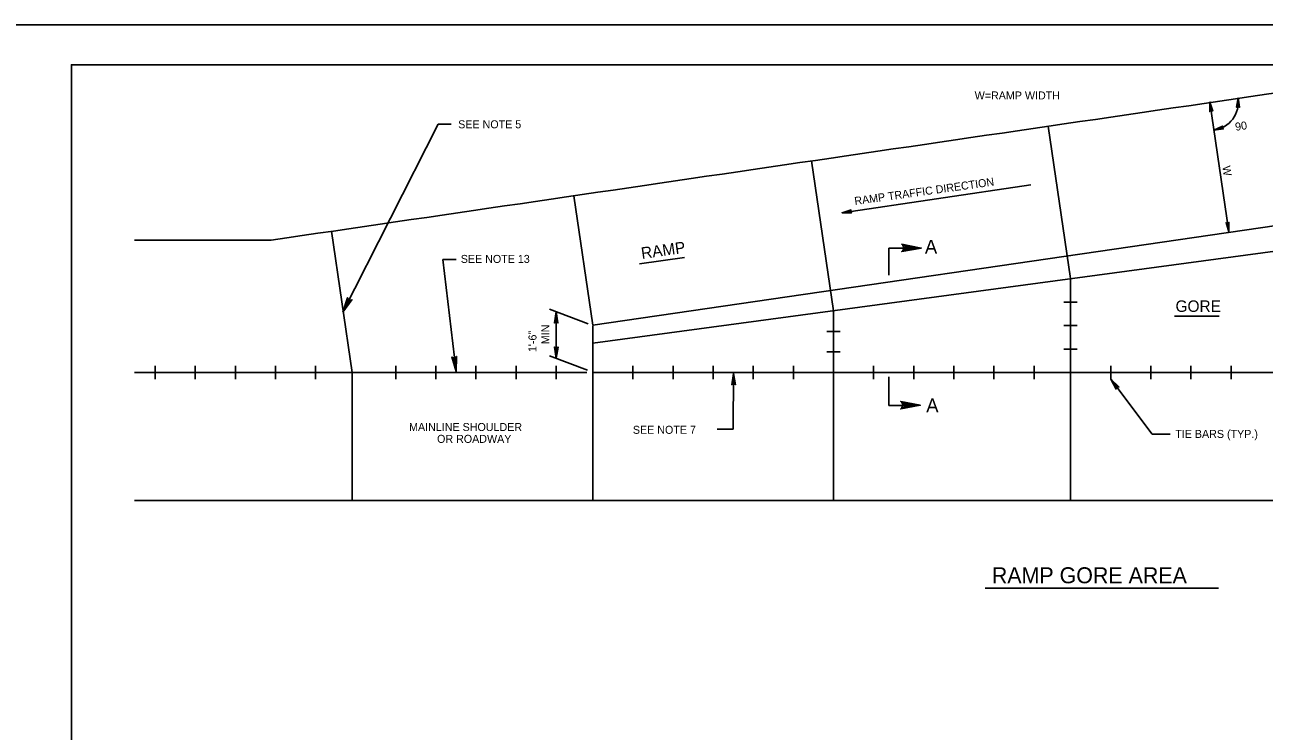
# Model space of a CAD drawing. Extents: x 638216 to 639962, y 297510 to 299292.
# Drawn here: x 639079.4 to 639544, y 299027.4 to 299292.2 of the extents above; entities that cross this region are included whole.
import ezdxf

# ---------------------------------------------------------------- set-up
doc = ezdxf.new("R2010")
doc.units = 0
for name, color, linetype in [('1', 7, 'Continuous'), ('2', 7, 'Continuous'), ('3', 7, 'Continuous'), ('PLT-BNDY', 7, 'Continuous')]:
    doc.layers.add(name, color=color, linetype=linetype)

msp = doc.modelspace()

# ---------------------------------------------------------------- linework, layer by layer
at = {"layer": '1'}
for p, q in [((639292.33, 299179.55), (639839.61, 299259.6)), ((639471.47, 299197.06), (639463.09, 299254.19)), ((639292.35, 299172.88), (639839.61, 299246.75)), ((639382.57, 299184.97), (639374.32, 299241.18)), ((639292.33, 299179.55), (639285.21, 299228.11)), ((639471.47, 299196.97), (639471.47, 299196.97)), ((639471.47, 299188.2), (639471.47, 299188.2)), ((639382.57, 299184.97), (639382.57, 299184.97)), ((639382.57, 299177.28), (639382.57, 299177.28)), ((639471.47, 299179.43), (639471.47, 299179.43)), ((639382.57, 299169.59), (639382.57, 299169.59)), ((639471.47, 299170.67), (639471.47, 299170.67)), ((639128.28, 299161.9), (639134.54, 299161.9)), ((639218.49, 299161.9), (639224.75, 299161.9)), ((639307.39, 299161.9), (639313.65, 299161.9)), ((639344.92, 299140.67), (639345.14, 299161.49)), ((639397.6, 299161.9), (639403.86, 299161.9)), ((639486.5, 299161.9), (639492.76, 299161.9)), ((639501.97, 299138.76), (639486.5, 299159.39)), ((639338.97, 299140.67), (639344.92, 299140.67))]:
    msp.add_line(p, q, dxfattribs=at)
msp.add_lwpolyline([(639882.88, 298713.24), (639882.88, 299277.24), (639096.88, 299277.24), (639096.88, 298713.24), (639882.88, 298713.24), (639882.88, 298739.6), (639682.88, 298739.6), (639682.88, 298804.28), (639882.88, 298804.28), (639882.88, 298833.24), (639682.88, 298833.24), (639682.88, 298713.24), (639761.69, 298713.24), (639761.69, 298739.6), (639761.69, 298713.24), (639838.69, 298713.24), (639838.69, 298739.6), (639838.69, 298727.28), (639882.88, 298727.28)], dxfattribs=at)
msp.add_lwpolyline([(639882.88, 298713.24), (639882.88, 299277.24), (639096.88, 299277.24), (639096.88, 298713.24), (639882.88, 298713.24), (639882.88, 298739.6), (639682.88, 298739.6), (639682.88, 298804.28), (639882.88, 298804.28), (639882.88, 298833.24), (639682.88, 298833.24), (639682.88, 298713.24), (639761.69, 298713.24), (639761.69, 298739.6), (639761.69, 298713.24), (639838.69, 298713.24), (639838.69, 298739.6), (639838.69, 298727.28), (639882.88, 298727.28)], dxfattribs=at)
msp.add_lwpolyline([(639882.88, 298713.24), (639882.88, 299277.24), (639096.88, 299277.24), (639096.88, 298713.24), (639882.88, 298713.24), (639882.88, 298739.6), (639682.88, 298739.6), (639682.88, 298804.28), (639882.88, 298804.28), (639882.88, 298833.24), (639682.88, 298833.24), (639682.88, 298713.24), (639761.69, 298713.24), (639761.69, 298739.6), (639761.69, 298713.24), (639838.69, 298713.24), (639838.69, 298739.6), (639838.69, 298727.28), (639882.88, 298727.28)], dxfattribs=at)
msp.add_lwpolyline([(639882.88, 298713.24), (639882.88, 299277.24), (639096.88, 299277.24), (639096.88, 298713.24), (639882.88, 298713.24), (639882.88, 298739.6), (639682.88, 298739.6), (639682.88, 298804.28), (639882.88, 298804.28), (639882.88, 298833.24), (639682.88, 298833.24), (639682.88, 298713.24), (639761.69, 298713.24), (639761.69, 298739.6), (639761.69, 298713.24), (639838.69, 298713.24), (639838.69, 298739.6), (639838.69, 298727.28), (639882.88, 298727.28)], dxfattribs=at)
msp.add_lwpolyline([(639882.88, 298713.24), (639882.88, 299277.24), (639096.88, 299277.24), (639096.88, 298713.24), (639882.88, 298713.24), (639882.88, 298739.6), (639682.88, 298739.6), (639682.88, 298804.28), (639882.88, 298804.28), (639882.88, 298833.24), (639682.88, 298833.24), (639682.88, 298713.24), (639761.69, 298713.24), (639761.69, 298739.6), (639761.69, 298713.24), (639838.69, 298713.24), (639838.69, 298739.6), (639838.69, 298727.28), (639882.88, 298727.28)], dxfattribs=at)
msp.add_lwpolyline([(639882.88, 298713.24), (639882.88, 299277.24), (639096.88, 299277.24), (639096.88, 298713.24), (639882.88, 298713.24), (639882.88, 298739.6), (639682.88, 298739.6), (639682.88, 298804.28), (639882.88, 298804.28), (639882.88, 298833.24), (639682.88, 298833.24), (639682.88, 298713.24), (639761.69, 298713.24), (639761.69, 298739.6), (639761.69, 298713.24), (639838.69, 298713.24), (639838.69, 298739.6), (639838.69, 298727.28), (639882.88, 298727.28)], dxfattribs=at)
at = {"layer": '2'}
for p, q in [((639234.33, 299255.03), (639198.69, 299184.5)), ((639239.26, 299255.03), (639234.33, 299255.03)), ((639385.78, 299221.78), (639456.57, 299232.18)), ((639202.14, 299161.9), (639194.39, 299214.8)), ((639171.79, 299211.48), (639120.56, 299211.48)), ((639403.26, 299198.38), (639403.26, 299208.53)), ((639403.26, 299208.53), (639412.97, 299208.53)), ((639241.11, 299204.17), (639236.18, 299204.17)), ((639236.18, 299204.17), (639241.09, 299162.24)), ((639309.9, 299202.6), (639326.68, 299205.03)), ((639471.47, 299161.9), (639471.47, 299197.06)), ((639276.14, 299185.61), (639290.55, 299180.05)), ((639473.97, 299188.2), (639468.96, 299188.2)), ((639278.62, 299167.2), (639278.62, 299184.65)), ((639382.57, 299161.9), (639382.57, 299185.06)), ((639510.38, 299182.98), (639527.12, 299182.98)), ((639292.35, 299161.9), (639292.35, 299179.36)), ((639385.07, 299177.28), (639380.06, 299177.28)), ((639473.97, 299179.43), (639468.96, 299179.43)), ((639276.14, 299168.16), (639290.3, 299162.69)), ((639385.07, 299169.59), (639380.06, 299169.59)), ((639473.97, 299170.67), (639468.96, 299170.67)), ((639128.28, 299159.39), (639128.28, 299164.41)), ((639143.31, 299159.39), (639143.31, 299164.41)), ((639158.35, 299159.39), (639158.35, 299164.41)), ((639173.38, 299159.39), (639173.38, 299164.41)), ((639188.42, 299159.39), (639188.42, 299164.41)), ((639218.49, 299159.39), (639218.49, 299164.41)), ((639233.52, 299159.39), (639233.52, 299164.41)), ((639248.56, 299159.39), (639248.56, 299164.41)), ((639263.6, 299159.39), (639263.6, 299164.41)), ((639278.63, 299159.39), (639278.63, 299164.41)), ((639307.39, 299159.39), (639307.39, 299164.41)), ((639322.42, 299159.39), (639322.42, 299164.41)), ((639337.46, 299159.39), (639337.46, 299164.41)), ((639352.49, 299159.39), (639352.49, 299164.41)), ((639367.53, 299159.39), (639367.53, 299164.41)), ((639397.6, 299159.39), (639397.6, 299164.41)), ((639412.64, 299159.39), (639412.64, 299164.41)), ((639427.67, 299159.39), (639427.67, 299164.41)), ((639442.71, 299159.39), (639442.71, 299164.41)), ((639457.74, 299159.39), (639457.74, 299164.41)), ((639486.5, 299159.39), (639486.5, 299164.41)), ((639501.54, 299159.39), (639501.54, 299164.41)), ((639516.57, 299159.39), (639516.57, 299164.41)), ((639531.61, 299159.39), (639531.61, 299164.41)), ((639290.06, 299161.9), (639120.56, 299161.9)), ((639202.14, 299161.9), (639202.14, 299113.9)), ((639292.35, 299161.9), (639292.35, 299113.9)), ((639839.61, 299161.9), (639292.35, 299161.9)), ((639382.57, 299161.9), (639382.57, 299113.9)), ((639403.26, 299149.49), (639403.26, 299160.29)), ((639471.47, 299161.9), (639471.47, 299113.9)), ((639403.26, 299149.49), (639412.97, 299149.49)), ((639508.79, 299138.76), (639501.97, 299138.76)), ((639875.5, 299113.9), (639120.56, 299113.9)), ((639439.38, 299080.98), (639526.89, 299080.98))]:
    msp.add_line(p, q, dxfattribs=at)
for points in [[(639533.86, 299261.49), (639534.09, 299261.61), (639534.24, 299264.83), (639533.86, 299261.49), (639533.7, 299261.31), (639534.24, 299264.83), (639534.43, 299261.61), (639534.67, 299261.5), (639534.24, 299264.83), (639534.83, 299261.32), (639534.67, 299261.5)], [(639523.74, 299259.93), (639523.95, 299260.07), (639523.66, 299263.28), (639523.74, 299259.93), (639523.6, 299259.72), (639523.66, 299263.28), (639524.29, 299260.12), (639524.53, 299260.04), (639523.66, 299263.28), (639524.72, 299259.88), (639524.53, 299260.04)], [(639528.51, 299253.3), (639528.34, 299253.49), (639525.21, 299252.7), (639528.51, 299253.3), (639528.74, 299253.21), (639525.21, 299252.7), (639528.23, 299253.82), (639528.27, 299254.07), (639525.21, 299252.7), (639528.4, 299254.28), (639528.27, 299254.07)], [(639389.13, 299221.85), (639388.99, 299222.08), (639385.78, 299221.78), (639389.13, 299221.85), (639389.33, 299221.74), (639385.78, 299221.78), (639388.92, 299222.4), (639389.01, 299222.66), (639385.78, 299221.78), (639389.17, 299222.84), (639389.01, 299222.66)], [(639529.89, 299217.89), (639530.14, 299217.81), (639530.79, 299214.65), (639529.89, 299217.89), (639529.71, 299218.05), (639530.79, 299214.65), (639530.48, 299217.86), (639530.69, 299218.01), (639530.79, 299214.65), (639530.82, 299218.21), (639530.69, 299218.01)], [(639408.54, 299209.57), (639408.77, 299209), (639415.44, 299208.54), (639408.54, 299209.57), (639408.15, 299209.97), (639415.44, 299208.54), (639408.77, 299208.14), (639408.54, 299207.57), (639415.44, 299208.54), (639408.15, 299207.17), (639408.54, 299207.57)], [(639201.69, 299188.97), (639201.26, 299188.96), (639198.69, 299184.5), (639201.69, 299188.97), (639202.03, 299189.11), (639198.69, 299184.5), (639200.78, 299189.2), (639200.52, 299189.54), (639198.69, 299184.5), (639200.42, 299189.92), (639200.52, 299189.54)], [(639278.13, 299180.66), (639278.4, 299180.79), (639278.62, 299184.65), (639278.13, 299180.66), (639277.93, 299180.44), (639278.62, 299184.65), (639278.81, 299180.79), (639279.09, 299180.66), (639278.62, 299184.65), (639279.29, 299180.44), (639279.09, 299180.66)], [(639279.12, 299171.19), (639278.84, 299171.05), (639278.62, 299167.2), (639279.12, 299171.19), (639279.31, 299171.41), (639278.62, 299167.2), (639278.43, 299171.05), (639278.15, 299171.19), (639278.62, 299167.2), (639277.96, 299171.41), (639278.15, 299171.19)], [(639241.11, 299167.62), (639240.75, 299167.38), (639241.09, 299162.24), (639241.11, 299167.62), (639241.31, 299167.92), (639241.09, 299162.24), (639240.21, 299167.31), (639239.81, 299167.45), (639241.09, 299162.24), (639239.52, 299167.7), (639239.81, 299167.45)], [(639344.65, 299157.5), (639344.92, 299157.63), (639345.14, 299161.49), (639344.65, 299157.5), (639344.46, 299157.28), (639345.14, 299161.49), (639345.34, 299157.63), (639345.61, 299157.5), (639345.14, 299161.49), (639345.81, 299157.28), (639345.61, 299157.5)], [(639488.53, 299155.91), (639488.66, 299156.19), (639486.5, 299159.39), (639488.53, 299155.91), (639488.5, 299155.62), (639486.5, 299159.39), (639488.99, 299156.44), (639489.29, 299156.5), (639486.5, 299159.39), (639489.58, 299156.44), (639489.29, 299156.5)], [(639408.18, 299150.63), (639408.42, 299150.06), (639415.08, 299149.61), (639408.18, 299150.63), (639407.8, 299151.03), (639415.08, 299149.61), (639408.42, 299149.2), (639408.18, 299148.64), (639415.08, 299149.61), (639407.8, 299148.23), (639408.18, 299148.64)]]:
    msp.add_lwpolyline(points, dxfattribs=at)
msp.add_spline([(639171.79, 299211.48), (639544.88, 299266.17), (639589.83, 299272.75)], degree=3, dxfattribs=at)
at = {"layer": '3'}
msp.add_line((639530.79, 299214.65), (639523.66, 299263.28), dxfattribs=at)
msp.add_arc((639523.66, 299263.28), 10.69, 278.3359, 8.3222, dxfattribs=at)
at = {"layer": 'PLT-BNDY'}
msp.add_lwpolyline([(639056.88, 299292.24), (639897.88, 299292.24), (639897.88, 298698.24), (639056.88, 298698.24)], close=True, dxfattribs=at)

# ---------------------------------------------------------------- texts
at = {"layer": '1'}
for s, height, p in [('GORE', 4.32, (639510.79, 299184.58)), ('MAINLINE SHOULDER', 3, (639223.48, 299139.92)), ('OR ROADWAY', 3, (639233.97, 299135.48))]:
    msp.add_text(s, height=height, dxfattribs=at).set_placement(p)
at = {"layer": '3'}
for s, height, p in [('W=RAMP WIDTH', 3, (639435.5, 299264.23)), ('SEE NOTE 5', 3, (639241.89, 299253.43)), ('A', 5.18, (639416.83, 299206.42)), ('SEE NOTE 13', 3, (639242.85, 299202.95)), ('A', 5.18, (639417.33, 299146.94)), ('SEE NOTE 7', 3, (639307.37, 299138.87)), ('TIE BARS (TYP.) ', 3, (639510.69, 299137.33)), ('RAMP GORE AREA', 6, (639441.93, 299082.83))]:
    msp.add_text(s, height=height, dxfattribs=at).set_placement(p)
for s, height, rotation, p in [('90', 3, 8.3392, (639533.35, 299252.48)), ('W', 3, 278.3359, (639528.34, 299239.14)), ('RAMP TRAFFIC DIRECTION', 3, 8, (639390.63, 299224.64)), ('RAMP', 4.32, 8, (639310.76, 299204.43)), ('1\'-6"', 3, 90, (639271.24, 299169.51)), ('MIN', 3, 90, (639276.02, 299172.46))]:
    msp.add_text(s, height=height, rotation=rotation, dxfattribs=at).set_placement(p)

doc.saveas('drawing.dxf')
